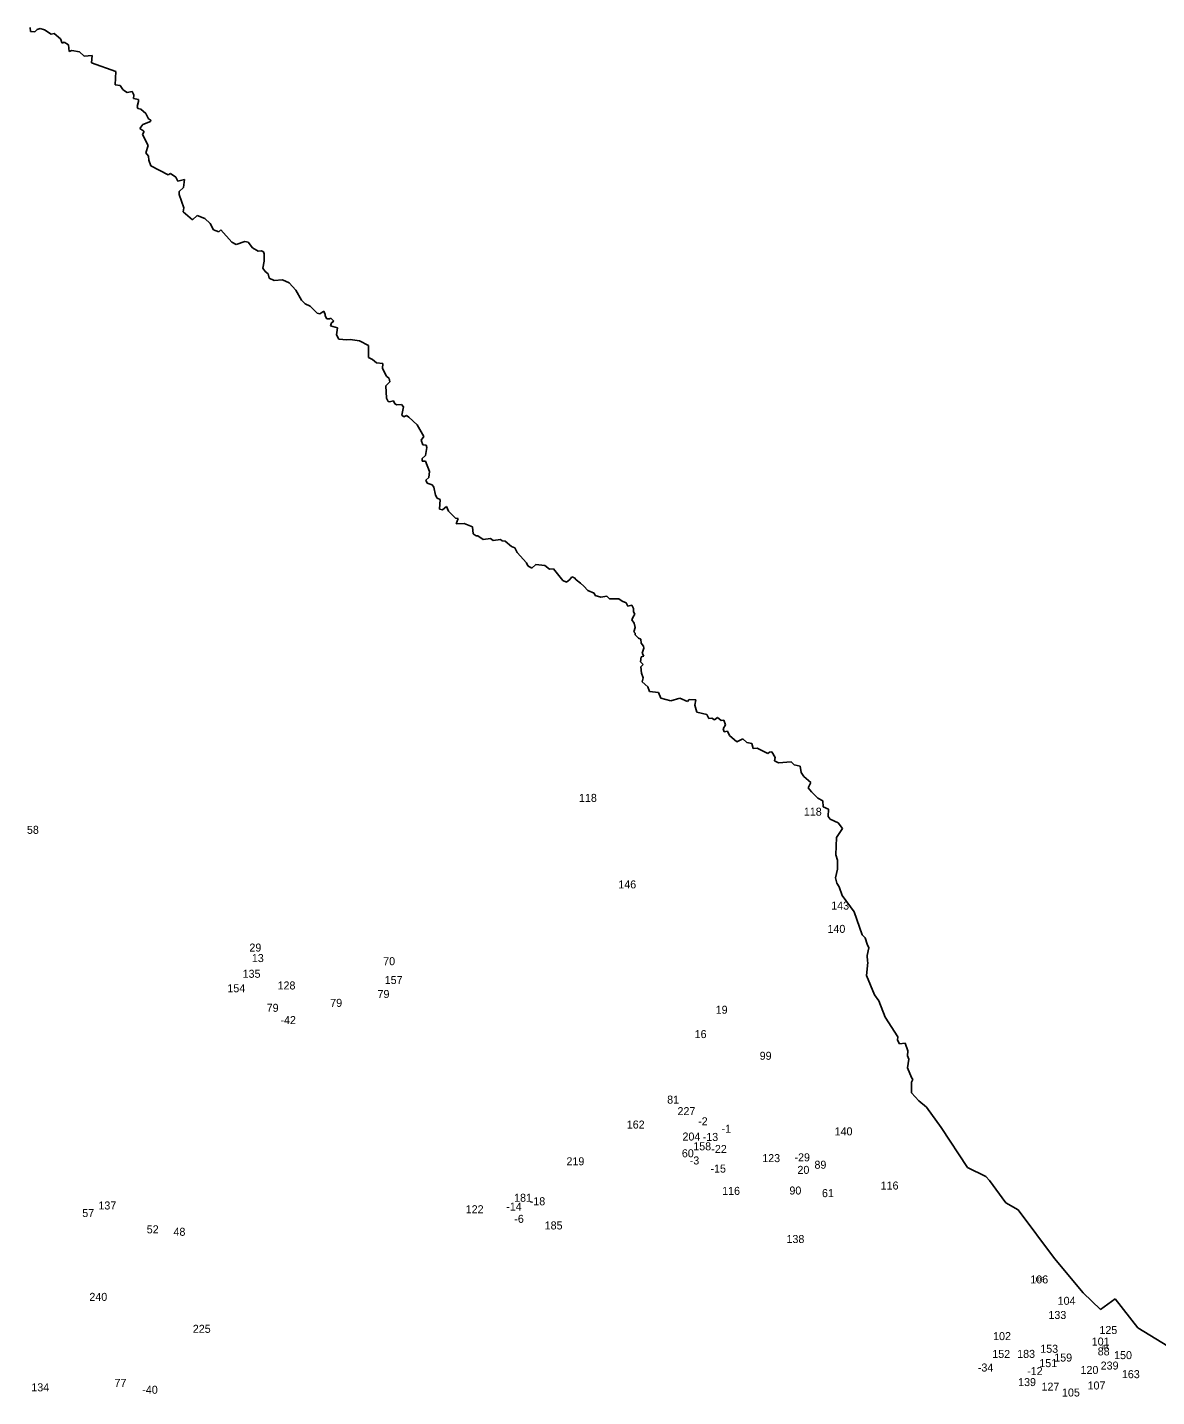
# Model space of a CAD drawing. Extents: x -788870 to -783053, y -967261 to -964403.
# Drawn here: x -785825 to -784414, y -966171 to -964460 of the extents above; entities that cross this region are included whole.
import ezdxf

# ---------------------------------------------------------------- set-up
doc = ezdxf.new("R2010")
doc.units = 0
doc.layers.add('Vrstva 13', color=7, linetype='Continuous')
doc.layers.add('Vrstva 15', color=7, linetype='Continuous')

msp = doc.modelspace()

# ---------------------------------------------------------------- linework, layer by layer
at = {"layer": 'Vrstva 13'}
for p, q in [((-785821.19, -964465.35), (-785821.85, -964460.05)), ((-785815.89, -964465.79), (-785821.19, -964465.35)), ((-785813.02, -964462.7), (-785815.89, -964465.79)), ((-785809.27, -964461.37), (-785813.02, -964462.7)), ((-785803.75, -964462.92), (-785809.27, -964461.37)), ((-785795.36, -964468.66), (-785803.75, -964462.92)), ((-785791.61, -964467.56), (-785795.36, -964468.66)), ((-785783.88, -964474.4), (-785791.61, -964467.56)), ((-785781.68, -964479.7), (-785783.88, -964474.4)), ((-785779.03, -964478.6), (-785781.68, -964479.7)), ((-785773.95, -964481.69), (-785779.03, -964478.6)), ((-785772.84, -964490.08), (-785773.95, -964481.69)), ((-785769.53, -964488.98), (-785772.84, -964490.08)), ((-785760.04, -964490.74), (-785769.53, -964488.98)), ((-785754.3, -964495.82), (-785760.04, -964490.74)), ((-785744.15, -964495.38), (-785754.3, -964495.82)), ((-785744.9, -964504.32), (-785744.15, -964495.38)), ((-785744.9, -964504.32), (-785714.42, -964515.19)), ((-785714.42, -964515.19), (-785715.64, -964531.85)), ((-785715.64, -964531.85), (-785708.99, -964532.86)), ((-785708.99, -964532.86), (-785705.87, -964537.86)), ((-785705.87, -964537.86), (-785703.7, -964539.53)), ((-785703.7, -964539.53), (-785700.37, -964541.34)), ((-785700.37, -964541.34), (-785694.36, -964540.25)), ((-785694.36, -964540.25), (-785692.4, -964543.44)), ((-785691.97, -964544.67), (-785692.62, -964548.87)), ((-785692.62, -964548.87), (-785686.32, -964550.32)), ((-785692.4, -964543.44), (-785691.97, -964544.67)), ((-785686.32, -964550.32), (-785686.17, -964552.79)), ((-785686.17, -964552.79), (-785687.91, -964558.94)), ((-785687.91, -964558.94), (-785687.19, -964561.55)), ((-785687.19, -964561.55), (-785683.49, -964562.2)), ((-785683.49, -964562.2), (-785677.05, -964567.85)), ((-785677.05, -964567.85), (-785673.87, -964574.37)), ((-785681.03, -964581.55), (-785684.58, -964586.33)), ((-785671.26, -964577.63), (-785681.03, -964581.55)), ((-785673.87, -964574.37), (-785670.75, -964575.9)), ((-785670.75, -964575.9), (-785671.26, -964577.63)), ((-785684.58, -964586.33), (-785679.59, -964589.81)), ((-785679.44, -964591.18), (-785681.11, -964594.01)), ((-785681.11, -964594.01), (-785674.23, -964607.7)), ((-785679.59, -964589.81), (-785679.44, -964591.18)), ((-785674.23, -964607.7), (-785677.06, -964616.83)), ((-785677.06, -964616.83), (-785673.8, -964620.96)), ((-785673.8, -964620.96), (-785673.44, -964625.96)), ((-785673.44, -964625.96), (-785671.05, -964633.13)), ((-785671.05, -964633.13), (-785649.03, -964644.29)), ((-785649.03, -964644.29), (-785646.28, -964642.77)), ((-785646.28, -964642.77), (-785639.69, -964647.19)), ((-785639.69, -964647.19), (-785637.08, -964652.11)), ((-785637.08, -964652.11), (-785628.68, -964650.37)), ((-785628.68, -964650.37), (-785630.13, -964660.23)), ((-785630.13, -964660.23), (-785635.35, -964665.15)), ((-785635.35, -964665.15), (-785635.35, -964668.92)), ((-785635.35, -964668.92), (-785629.84, -964685.73)), ((-785629.84, -964685.73), (-785630.42, -964690.65)), ((-785630.42, -964690.65), (-785618.83, -964700.5)), ((-785618.83, -964700.5), (-785613.04, -964695.29)), ((-785613.04, -964695.29), (-785603.19, -964698.77)), ((-785603.19, -964698.77), (-785596.53, -964705.14)), ((-785596.53, -964705.14), (-785592.76, -964713.25)), ((-785592.76, -964713.25), (-785586.1, -964715.57)), ((-785586.1, -964715.57), (-785583.49, -964713.25)), ((-785583.49, -964713.25), (-785569.59, -964728.61)), ((-785569.59, -964728.61), (-785564.38, -964731.51)), ((-785564.38, -964731.51), (-785553.37, -964727.74)), ((-785553.37, -964727.74), (-785549.31, -964728.61)), ((-785549.31, -964728.61), (-785543.81, -964735.57)), ((-785543.81, -964735.57), (-785536.86, -964739.91)), ((-785536.86, -964739.91), (-785532.51, -964739.33)), ((-785532.51, -964739.33), (-785530.2, -964740.78)), ((-785529.32, -964752.16), (-785530.85, -964760.99)), ((-785530.2, -964740.78), (-785529.33, -964743.1)), ((-785529.33, -964743.1), (-785529.32, -964752.16)), ((-785530.85, -964760.99), (-785528.17, -964765.27)), ((-785528.17, -964765.27), (-785524.11, -964767.88)), ((-785524.11, -964767.88), (-785522.81, -964773.38)), ((-785522.81, -964773.38), (-785516.65, -964776.57)), ((-785516.65, -964776.57), (-785506.37, -964775.7)), ((-785506.37, -964775.7), (-785498.11, -964779.32)), ((-785498.11, -964779.32), (-785489.57, -964788.45)), ((-785489.57, -964788.45), (-785482.48, -964801.2)), ((-785482.48, -964801.2), (-785478.13, -964805.47)), ((-785478.13, -964805.47), (-785471.9, -964808.52)), ((-785471.9, -964808.52), (-785463.14, -964817.43)), ((-785463.14, -964817.43), (-785459.66, -964818.16)), ((-785459.66, -964818.16), (-785454.59, -964814.61)), ((-785454.59, -964814.61), (-785453, -964818.96)), ((-785453, -964818.96), (-785453.22, -964820.69)), ((-785453.22, -964820.69), (-785451.12, -964824.17)), ((-785451.12, -964824.17), (-785447.79, -964824.53)), ((-785447.79, -964824.53), (-785445.9, -964823.3)), ((-785445.9, -964823.3), (-785442.28, -964827.43)), ((-785445.18, -964829.32), (-785446.34, -964832.94)), ((-785446.34, -964832.94), (-785437.5, -964835.55)), ((-785442.28, -964827.43), (-785445.18, -964829.32)), ((-785437.5, -964835.55), (-785438.66, -964844.31)), ((-785438.66, -964844.31), (-785435.83, -964849.67)), ((-785435.83, -964849.67), (-785426.13, -964850.76)), ((-785426.13, -964850.76), (-785421.93, -964850.32)), ((-785421.93, -964850.32), (-785410.2, -964852)), ((-785410.2, -964852), (-785398.9, -964857.86)), ((-785398.9, -964857.86), (-785398.75, -964872.79)), ((-785398.75, -964872.79), (-785393.68, -964874.96)), ((-785393.68, -964874.96), (-785388.7, -964879.3)), ((-785388.7, -964879.3), (-785381.09, -964879.96)), ((-785381.09, -964879.96), (-785381.31, -964886.55)), ((-785381.31, -964886.55), (-785376.31, -964896.18)), ((-785372.19, -964903.14), (-785377.04, -964908.06)), ((-785377.04, -964908.06), (-785376.45, -964923.42)), ((-785376.31, -964896.18), (-785373.13, -964898.79)), ((-785373.13, -964898.79), (-785372.19, -964903.14)), ((-785376.45, -964923.42), (-785374.13, -964927.48)), ((-785374.13, -964927.48), (-785372.61, -964928.06)), ((-785372.61, -964928.06), (-785367.47, -964926.68)), ((-785367.47, -964926.68), (-785365.8, -964930.74)), ((-785365.8, -964930.74), (-785363.34, -964931.68)), ((-785363.34, -964931.68), (-785357.55, -964931.46)), ((-785357.55, -964931.46), (-785355.23, -964934.5)), ((-785355.23, -964934.5), (-785357.4, -964944.86)), ((-785357.4, -964944.86), (-785354.87, -964946.88)), ((-785354.87, -964946.88), (-785351.32, -964945.22)), ((-785351.32, -964945.22), (-785348.57, -964947.1)), ((-785348.57, -964947.1), (-785338.14, -964956.74)), ((-785338.14, -964956.74), (-785329.67, -964971.59)), ((-785329.67, -964971.59), (-785333.22, -964976.08)), ((-785333.22, -964976.08), (-785330.97, -964981.73)), ((-785327.57, -964995.35), (-785331.9, -964999.05)), ((-785330.97, -964981.73), (-785326.77, -964982.38)), ((-785326.05, -964985.21), (-785327.57, -964995.35)), ((-785326.77, -964982.38), (-785326.05, -964985.21)), ((-785331.9, -964999.05), (-785331.61, -965002.38)), ((-785331.61, -965002.38), (-785327.63, -965002.31)), ((-785327.63, -965002.31), (-785322.7, -965015.13)), ((-785323.5, -965022.81), (-785327.19, -965025.99)), ((-785327.19, -965025.99), (-785325.46, -965029.76)), ((-785325.46, -965029.76), (-785319.3, -965031.79)), ((-785322.7, -965015.13), (-785323.5, -965022.81)), ((-785319.3, -965031.79), (-785317.35, -965034.69)), ((-785317.35, -965034.69), (-785315.03, -965044.54)), ((-785315.03, -965044.54), (-785312.86, -965048.45)), ((-785312.86, -965048.45), (-785309.38, -965050.05)), ((-785309.38, -965050.05), (-785310.25, -965062.36)), ((-785310.25, -965062.36), (-785306.34, -965062.94)), ((-785306.34, -965062.94), (-785301.41, -965058.88)), ((-785301.41, -965058.88), (-785298.81, -965064.82)), ((-785298.81, -965064.82), (-785289.97, -965073.37)), ((-785289.97, -965073.37), (-785286.64, -965074.1)), ((-785286.64, -965074.1), (-785289.39, -965080.47)), ((-785289.39, -965080.47), (-785279.4, -965080.33)), ((-785279.4, -965080.33), (-785268.83, -965084.38)), ((-785268.83, -965084.38), (-785267.96, -965093.22)), ((-785267.96, -965093.22), (-785264.48, -965095.39)), ((-785264.48, -965095.39), (-785262.16, -965095.68)), ((-785262.16, -965095.68), (-785255.65, -965100.32)), ((-785255.65, -965100.32), (-785246.52, -965098.87)), ((-785246.52, -965098.87), (-785242.9, -965101.48)), ((-785242.9, -965101.48), (-785234.06, -965100.03)), ((-785234.06, -965100.03), (-785231.75, -965101.91)), ((-785231.75, -965101.91), (-785227.98, -965102.06)), ((-785227.98, -965102.06), (-785220.16, -965109.01)), ((-785220.16, -965109.01), (-785215.96, -965110.75)), ((-785215.96, -965110.75), (-785212.92, -965116.4)), ((-785212.92, -965116.4), (-785201.62, -965129.15)), ((-785201.62, -965129.15), (-785199.59, -965132.92)), ((-785199.59, -965132.92), (-785194.81, -965135.81)), ((-785194.81, -965135.81), (-785189.74, -965131.32)), ((-785189.74, -965131.32), (-785178.59, -965132.77)), ((-785178.59, -965132.77), (-785172.79, -965137.11)), ((-785172.79, -965137.11), (-785167.87, -965136.82)), ((-785167.87, -965136.82), (-785155.85, -965151.46)), ((-785151.65, -965153.49), (-785147.16, -965150.3)), ((-785147.16, -965150.3), (-785144.98, -965146.82)), ((-785144.98, -965146.82), (-785141.51, -965147.99)), ((-785141.51, -965147.99), (-785139.48, -965150.74)), ((-785139.48, -965150.74), (-785133.83, -965154.8)), ((-785155.85, -965151.46), (-785151.65, -965153.49)), ((-785133.83, -965154.8), (-785129.63, -965158.56)), ((-785129.63, -965158.56), (-785124.71, -965164.07)), ((-785124.71, -965164.07), (-785117.03, -965167.11)), ((-785117.03, -965167.11), (-785115.44, -965170.15)), ((-785115.44, -965170.15), (-785108.63, -965172.04)), ((-785108.63, -965172.04), (-785100.95, -965170.88)), ((-785100.95, -965170.88), (-785097.62, -965174.21)), ((-785097.62, -965174.21), (-785086.18, -965174.21)), ((-785086.18, -965174.21), (-785081.69, -965177.4)), ((-785081.69, -965177.4), (-785076.91, -965179.14)), ((-785076.91, -965179.14), (-785074.6, -965183.63)), ((-785074.6, -965183.63), (-785069.81, -965182.32)), ((-785069.81, -965182.32), (-785067.93, -965186.53)), ((-785068.21, -965196.81), (-785069.66, -965200.72)), ((-785069.66, -965200.72), (-785066.91, -965204.78)), ((-785065.9, -965193.62), (-785068.21, -965196.81)), ((-785067.93, -965186.53), (-785067.93, -965190.44)), ((-785067.93, -965190.44), (-785065.9, -965193.62)), ((-785065.75, -965210), (-785067.35, -965215.36)), ((-785067.35, -965215.36), (-785065.46, -965217.39)), ((-785066.91, -965204.78), (-785065.75, -965210)), ((-785065.46, -965217.39), (-785065.46, -965219.12)), ((-785065.46, -965219.12), (-785061.42, -965223.65)), ((-785061.42, -965223.65), (-785058.56, -965224.59)), ((-785058.56, -965224.59), (-785058.23, -965229.88)), ((-785058.23, -965229.88), (-785055.12, -965233.65)), ((-785055.01, -965236.04), (-785057, -965242.31)), ((-785055.12, -965233.65), (-785055.01, -965236.04)), ((-785058.31, -965247.01), (-785059.17, -965252.88)), ((-785059.17, -965252.88), (-785055.69, -965256.28)), ((-785054.97, -965246.07), (-785058.31, -965247.01)), ((-785057, -965242.31), (-785054.97, -965246.07)), ((-785055.69, -965256.28), (-785058.59, -965259.25)), ((-785058.59, -965259.25), (-785057.79, -965267.01)), ((-785057.79, -965267.01), (-785055.55, -965273.16)), ((-785055.55, -965273.16), (-785056.99, -965277.95)), ((-785056.99, -965277.95), (-785049.69, -965284.24)), ((-785049.69, -965284.24), (-785047.73, -965290.18)), ((-785047.73, -965290.18), (-785036.51, -965291.56)), ((-785036.51, -965291.56), (-785033.75, -965298.52)), ((-785033.75, -965298.52), (-785021.22, -965301.86)), ((-785021.22, -965301.86), (-785009.85, -965298.52)), ((-785009.85, -965298.52), (-785000.22, -965302.58)), ((-785000.22, -965302.58), (-784998.19, -965300.04)), ((-784998.19, -965300.04), (-784989.64, -965300.48)), ((-784989.64, -965300.48), (-784991.23, -965307.36)), ((-784991.23, -965307.36), (-784988.41, -965315.77)), ((-784988.41, -965315.77), (-784976.03, -965318.74)), ((-784976.03, -965318.74), (-784973.42, -965323.74)), ((-784973.42, -965323.74), (-784969.65, -965323.52)), ((-784969.65, -965323.52), (-784966.69, -965325.56)), ((-784966.69, -965325.56), (-784962.64, -965322.66)), ((-784962.64, -965322.66), (-784958.29, -965326.28)), ((-784958.29, -965326.28), (-784954.96, -965325.77)), ((-784952.64, -965331.64), (-784955.61, -965336.86)), ((-784955.61, -965336.86), (-784954.52, -965340.55)), ((-784954.96, -965325.77), (-784952.64, -965331.64)), ((-784954.52, -965340.55), (-784950.32, -965339.9)), ((-784950.32, -965339.9), (-784947.79, -965345.12)), ((-784947.79, -965345.12), (-784938.74, -965353.01)), ((-784938.74, -965353.01), (-784930.99, -965349.32)), ((-784930.99, -965349.32), (-784925.92, -965354.03)), ((-784925.92, -965354.03), (-784919.98, -965355.04)), ((-784919.98, -965355.04), (-784918.31, -965361.27)), ((-784918.31, -965361.27), (-784913.32, -965360.98)), ((-784913.32, -965360.98), (-784899.92, -965367.57)), ((-784899.92, -965367.57), (-784897.82, -965365.97)), ((-784897.82, -965365.97), (-784894.78, -965365.61)), ((-784894.78, -965365.61), (-784890.64, -965372.79)), ((-784890.64, -965372.79), (-784891.51, -965376.92)), ((-784891.51, -965376.92), (-784886.66, -965379.46)), ((-784886.66, -965379.46), (-784870.58, -965378.22)), ((-784870.58, -965378.22), (-784866.89, -965381.63)), ((-784866.89, -965381.63), (-784859.28, -965383.66)), ((-784859.28, -965383.66), (-784858.41, -965391.19)), ((-784858.41, -965391.19), (-784854.94, -965396.34)), ((-784854.94, -965396.34), (-784846.1, -965403.87)), ((-784846.1, -965403.87), (-784849.5, -965410.39)), ((-784849.5, -965410.39), (-784845.45, -965415.61)), ((-784845.45, -965415.61), (-784837.34, -965423.59)), ((-784837.34, -965423.59), (-784831.26, -965426.78)), ((-784831.26, -965426.78), (-784830.68, -965434.46)), ((-784830.68, -965434.46), (-784824.16, -965437.06)), ((-784824.16, -965437.06), (-784824.31, -965446.48)), ((-784824.31, -965446.48), (-784821.99, -965449.67)), ((-784821.99, -965449.67), (-784812, -965454.31)), ((-784812, -965454.31), (-784806.64, -965461.4)), ((-784813.88, -965472.71), (-784815.04, -965494.15)), ((-784806.64, -965461.4), (-784813.88, -965472.71)), ((-784815.04, -965494.15), (-784812.86, -965500.82)), ((-784812.86, -965500.82), (-784812.86, -965512.27)), ((-784812.86, -965512.27), (-784815.32, -965522.99)), ((-784815.32, -965522.99), (-784813.44, -965529.8)), ((-784813.44, -965529.8), (-784810.83, -965534.15)), ((-784810.83, -965534.15), (-784806.91, -965545.16)), ((-784806.91, -965545.16), (-784792.14, -965565.44)), ((-784792.14, -965565.44), (-784782.14, -965594.42)), ((-784782.14, -965594.42), (-784778.38, -965598.19)), ((-784778.38, -965598.19), (-784775.77, -965605.87)), ((-784775.77, -965605.87), (-784773.45, -965610.65)), ((-784773.45, -965610.65), (-784775.77, -965619.92)), ((-784774.76, -965628.76), (-784776.63, -965644.98)), ((-784775.77, -965619.92), (-784775.33, -965627.02)), ((-784775.33, -965627.02), (-784774.76, -965628.76)), ((-784776.63, -965644.98), (-784766.64, -965669.32)), ((-784766.64, -965669.32), (-784761.28, -965676.85)), ((-784761.28, -965676.85), (-784753.17, -965697.14)), ((-784753.17, -965697.14), (-784737.23, -965721.76)), ((-784737.23, -965721.76), (-784737.81, -965725.96)), ((-784737.81, -965725.96), (-784735.35, -965730.31)), ((-784735.35, -965730.31), (-784728.25, -965729.59)), ((-784728.25, -965729.59), (-784724.78, -965739.29)), ((-784724.78, -965739.29), (-784725.5, -965745.67)), ((-784725.5, -965745.67), (-784723.76, -965749.87)), ((-784723.76, -965749.87), (-784725.21, -965760.59)), ((-784725.21, -965760.59), (-784720.43, -965772.76)), ((-784720.43, -965772.76), (-784718.55, -965774.94)), ((-784718.55, -965774.94), (-784720.43, -965778.41)), ((-784720.43, -965778.41), (-784720.43, -965791.74)), ((-784720.43, -965791.74), (-784711.16, -965801.89)), ((-784711.16, -965801.89), (-784701.6, -965809.71)), ((-784701.6, -965809.71), (-784683.06, -965835.07)), ((-784650.34, -965884.89), (-784683.06, -965835.07)), ((-784627.45, -965896.49), (-784650.34, -965884.89)), ((-784622.82, -965901.41), (-784627.45, -965896.49)), ((-784602.54, -965929.24), (-784622.82, -965901.41)), ((-784586.89, -965937.93), (-784602.54, -965929.24)), ((-784586.89, -965937.93), (-784602.54, -965929.24)), ((-784541.7, -965998.79), (-784586.89, -965937.93)), ((-784541.7, -965998.79), (-784586.89, -965937.93)), ((-784505.64, -966041.68), (-784541.7, -965998.79)), ((-784505.64, -966041.68), (-784541.7, -965998.79)), ((-784484.34, -966062.69), (-784505.64, -966041.68)), ((-784484.34, -966062.69), (-784505.64, -966041.68)), ((-784465.95, -966049.36), (-784484.34, -966062.69)), ((-784465.95, -966049.36), (-784484.34, -966062.69)), ((-784437.41, -966085.29), (-784465.95, -966049.36)), ((-784437.41, -966085.29), (-784465.95, -966049.36)), ((-784392.37, -966113.11), (-784437.41, -966085.29))]:
    msp.add_line(p, q, dxfattribs=at)

# ---------------------------------------------------------------- texts
at = {"layer": 'Vrstva 15'}
for s, height, p in [('118', 10, (-785135.836, -965428.11)), ('118', 10, (-784854.836, -965445.32)), ('58', 10, (-785825.666, -965468.04)), ('146', 10, (-785086.71, -965536.25)), ('143', 10, (-784820.656, -965562.75)), ('140', 10, (-784825.317, -965591.81)), ('29', 10, (-785547.7, -965615.2)), ('13', 10, (-785544.631, -965628.34)), ('70', 10, (-785380.515, -965632.23)), ('135', 10, (-785556.161, -965647.95)), ('157', 10, (-785378.61, -965655.7)), ('154', 10, (-785575.217, -965666.05)), ('128', 10, (-785512.491, -965662.55)), ('79', 10, (-785387.588, -965673.27)), ('79', 10, (-785526.118, -965690.48)), ('79', 10, (-785446.688, -965684.31)), ('-42', 10, (-785508.926, -965705.83)), ('19', 10, (-784965.014, -965692.89)), ('16', 10, (-784991.314, -965723.33)), ('99', 10, (-784910.044, -965750.42)), ('81', 10, (-785025.651, -965805.23)), ('227', 10, (-785012.736, -965819.66)), ('162', 10, (-785076.134, -965836.41)), ('-2', 10, (-784986.95, -965832.31)), ('-1', 10, (-784957.664, -965841.68)), ('140', 10, (-784816.397, -965844.95)), ('204', 10, (-785006.502, -965851.38)), ('-13', 10, (-784981.224, -965851.9)), ('60', 10, (-785007.27, -965872.29)), ('158', 10, (-784993.031, -965863.58)), ('-22', 10, (-784970.46, -965866.93)), ('123', 10, (-784906.841, -965878.36)), ('-29', 10, (-784866.534, -965877.36)), ('219', 10, (-785151.484, -965882.32)), ('-3', 10, (-784997.44, -965881.29)), ('-15', 10, (-784971.514, -965891.45)), ('20', 10, (-784862.836, -965893.04)), ('89', 10, (-784841.58, -965886.63)), ('116', 10, (-784758.869, -965912.66)), ('181', 10, (-785216.926, -965927.92)), ('116', 10, (-784956.939, -965919.28)), ('90', 10, (-784872.87, -965918.85)), ('61', 10, (-784832.224, -965922.14)), ('57', 10, (-785756.526, -965947.02)), ('137', 10, (-785736.38, -965937.58)), ('122', 10, (-785277.391, -965942.24)), ('-14', 10, (-785226.73, -965938.9)), ('-18', 10, (-785197.364, -965932.27)), ('-6', 10, (-785216.684, -965954.26)), ('185', 10, (-785178.721, -965962.51)), ('52', 10, (-785675.996, -965967.37)), ('48', 10, (-785642.562, -965970.45)), ('138', 10, (-784876.541, -965979.47)), ('106', 10, (-784571.834, -966029.98)), ('106', 5, (-784566.382, -966027.48)), ('240', 10, (-785747.672, -966051.79)), ('104', 10, (-784537.687, -966056.69)), ('133', 10, (-784549.241, -966074.39)), ('225', 10, (-785618.406, -966091.73)), ('102', 10, (-784618.39, -966100.84)), ('125', 10, (-784485.511, -966093.22)), ('153', 10, (-784559.461, -966116.71)), ('101', 10, (-784495.125, -966107.62)), ('84', 5, (-784482.142, -966112.1)), ('152', 10, (-784619.371, -966123.15)), ('183', 10, (-784588.261, -966123.05)), ('151', 10, (-784560.586, -966134.58)), ('159', 10, (-784541.934, -966127.65)), ('88', 10, (-784487.626, -966119.96)), ('150', 10, (-784467.131, -966124.6)), ('-34', 10, (-784637.416, -966140.1)), ('-12', 10, (-784575.824, -966144.54)), ('120', 10, (-784509.111, -966143.16)), ('239', 10, (-784483.94, -966137.64)), ('163', 10, (-784457.424, -966148.4)), ('134', 10, (-785820.217, -966164.85)), ('77', 10, (-785716.304, -966159.38)), ('-40', 10, (-785681.566, -966167.9)), ('139', 10, (-784587.104, -966158.29)), ('127', 10, (-784557.86, -966164)), ('107', 10, (-784500.31, -966162.55)), ('105', 10, (-784532.27, -966171.32))]:
    msp.add_text(s, height=height, dxfattribs=at).set_placement(p)

doc.saveas('drawing.dxf')
